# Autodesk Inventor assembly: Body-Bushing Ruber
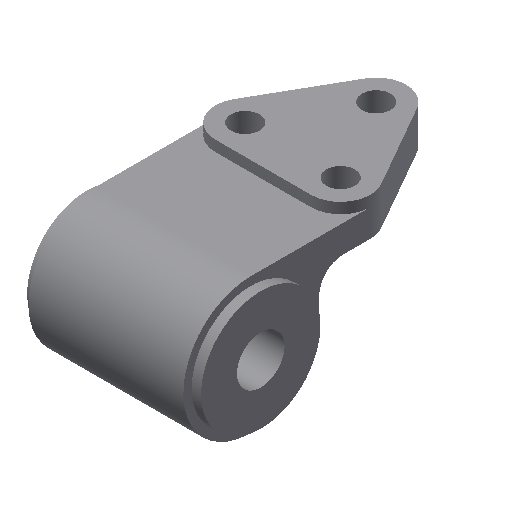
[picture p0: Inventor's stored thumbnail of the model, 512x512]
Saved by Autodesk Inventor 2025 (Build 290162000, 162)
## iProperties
Created: 2011-07
Part Number: Body-Bushing Ruber
Document SubType Name: Assembly
Designer: CadCim
Author: CadCim
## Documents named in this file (3)
- D:\CAD\Inventor\Autodesk Inventor 2025\Resources\2025\c09_Inv_2025_tut\c09_tut03_inv\Anti Vibration Mount\Body-Bushing Ruber.iam
- D:\CAD\Inventor\Autodesk Inventor 2025\Resources\2025\c09_Inv_2025_tut\c09_tut03_inv\Anti Vibration Mount\Body.ipt
- D:\CAD\Inventor\Autodesk Inventor 2025\Resources\2025\c09_Inv_2025_tut\c09_tut03_inv\Anti Vibration Mount\Bushing Rubber.ipt
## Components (3 placed, 2 different names)
1. Body:1 — Insert:1, Insert:2
2. Bushing Rubber:1 — Insert:1
3. Bushing Rubber:2 — Insert:2
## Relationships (2: Insert 2)
- Insert:1: Body:1 ↔ Bushing Rubber:1
- Insert:2: Body:1 ↔ Bushing Rubber:2
